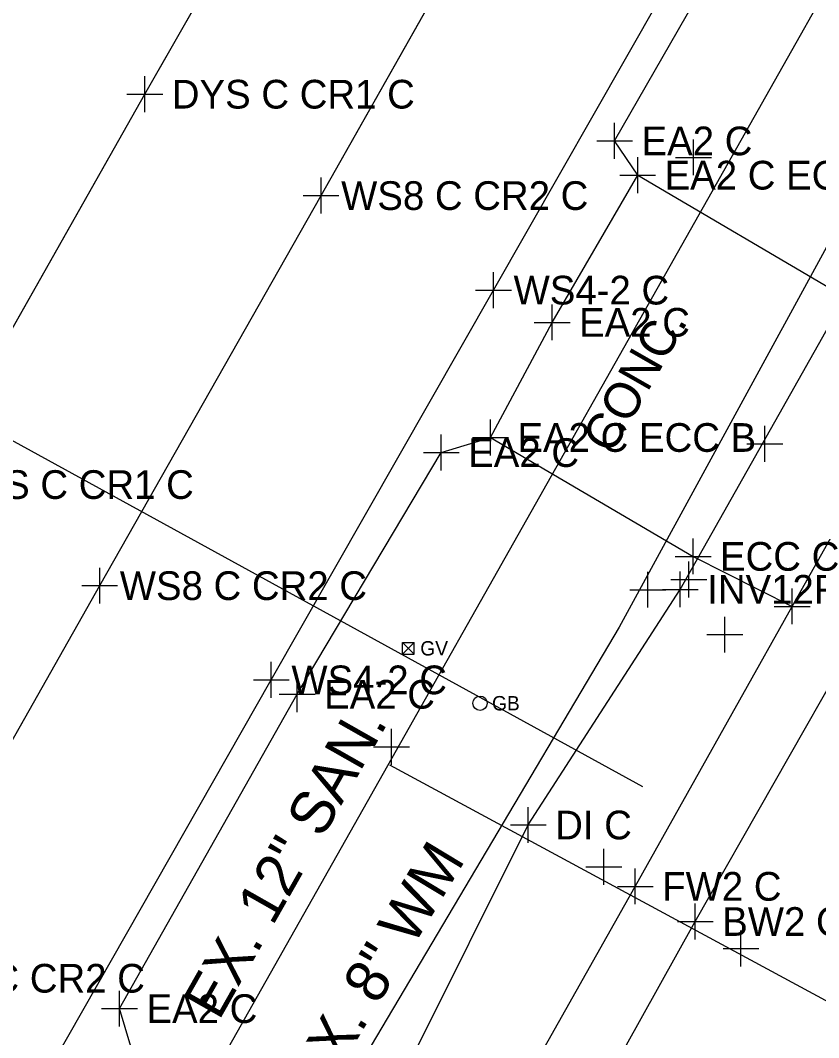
# Model space of a CAD drawing. Extents: x 1363693 to 1365209, y 422201 to 424153.
# Drawn here: x 1364106 to 1364150.5, y 422743.1 to 422799.8 of the extents above; entities that cross this region are included whole.
import ezdxf

# ---------------------------------------------------------------- set-up
doc = ezdxf.new("R2010")
doc.units = 0
for name, color, linetype in [('DR_X_Ditch', 7, 'Continuous'), ('DR_X_Storm_Sewer', 7, 'Continuous'), ('O-ALGN-BASELINE-WERK-CL-RW', 7, 'Continuous'), ('O-ALGN-TEXT-BASELINE-WERK-CL-RW', 7, 'Continuous'), ('OWNERS', 7, 'Continuous'), ('PM_X_Channelizing_Line', 7, 'Continuous'), ('PM_X_CL_Double_Solid', 7, 'Continuous'), ('PM_X_Edge_Line', 7, 'Continuous'), ('RD_X_Text', 7, 'Continuous'), ('SV_X_Original_Ground', 7, 'Continuous'), ('SV_X_Shot_Marker', 7, 'Continuous'), ('UT_X_Gas', 7, 'Continuous'), ('UT_X_Gas_Cells', 7, 'Continuous'), ('UT_X_Gas_Text', 7, 'Continuous'), ('UT_X_Sanitary_Line', 7, 'Continuous'), ('UT_X_Sanitary_Text', 7, 'Continuous'), ('UT_X_Water', 7, 'Continuous'), ('UT_X_Water_Text', 7, 'Continuous')]:
    doc.layers.add(name, color=color, linetype=linetype)

msp = doc.modelspace()

# ---------------------------------------------------------------- linework, layer by layer
at = {"layer": 'DR_X_Ditch'}
for p, q in [((1364134.344, 422754.934), (1364142.823, 422768.071)), ((1364134.344, 422754.934), (1364142.823, 422768.071)), ((1364125.178, 422736.61), (1364134.344, 422754.934)), ((1364125.178, 422736.61), (1364134.344, 422754.934))]:
    msp.add_line(p, q, dxfattribs=at)
at = {"layer": 'DR_X_Storm_Sewer'}
msp.add_line((1364142.823, 422768.071), (1364152.801, 422785.755), dxfattribs=at)
msp.add_line((1364142.823, 422768.071), (1364152.801, 422785.755), dxfattribs=at)
at = {"layer": 'O-ALGN-BASELINE-WERK-CL-RW'}
for points in [[(1364063.861, 422708.444), (1364075.973, 422730.252), (1364088.269, 422752.078), (1364100.636, 422773.911), (1364112.961, 422795.674), (1364125.29, 422817.23)], [(1364073.278, 422703.065), (1364085.603, 422724.652), (1364098.051, 422746.39), (1364110.44, 422768.276), (1364122.785, 422790.021), (1364135.008, 422811.616)]]:
    msp.add_lwpolyline(points, dxfattribs=at)
at = {"layer": 'O-ALGN-TEXT-BASELINE-WERK-CL-RW'}
for points in [[(1364106.881, 422684.697), (1364119.186, 422706.188), (1364124.526, 422715.531), (1364131.747, 422728.163), (1364132.791, 422730.069), (1364143.66, 422749.553), (1364152.461, 422765.008), (1364156.109, 422771.56), (1364160.497, 422779.388), (1364168.274, 422793.373), (1364180.613, 422814.721), (1364181.642, 422816.657), (1364190.312, 422832.027), (1364193.051, 422836.798), (1364205.158, 422858.42), (1364210.927, 422868.703), (1364217.538, 422880.583), (1364219, 422883.263), (1364226.216, 422896.876), (1364226.216, 422896.876), (1364230.124, 422904.765), (1364230.124, 422904.765), (1364238.068, 422921.555)], [(1364103.528, 422686.802), (1364115.786, 422708.146), (1364121.111, 422717.426), (1364128.281, 422730.151), (1364129.454, 422732.257), (1364140.312, 422751.513), (1364149.061, 422767.123), (1364152.636, 422773.448), (1364157.186, 422781.325), (1364164.964, 422795.393), (1364177.23, 422816.837)]]:
    msp.add_lwpolyline(points, dxfattribs=at)
at = {"layer": 'OWNERS'}
for points in [[(1364084.38, 422697.084), (1364096.639, 422718.672), (1364099.659, 422723.794), (1364104.078, 422727.14), (1364111.127, 422739.357), (1364112.498, 422741.524), (1364111.547, 422744.697), (1364121.455, 422762.22), (1364129.492, 422775.694), (1364132.238, 422776.536), (1364135.676, 422782.955), (1364140.445, 422791.159), (1364139.16, 422793.068), (1364146.3, 422805.509)], [(1364140.445, 422791.159), (1364151.778, 422784.5), (1364157.186, 422781.325)], [(1364132.238, 422776.536), (1364143.536, 422769.908), (1364149.061, 422767.123)]]:
    msp.add_lwpolyline(points, dxfattribs=at)
at = {"layer": 'PM_X_Channelizing_Line'}
for p, q in [((1364112.961, 422795.674), (1364125.29, 422817.23)), ((1364122.785, 422790.021), (1364135.008, 422811.616)), ((1364122.785, 422790.021), (1364135.008, 422811.616)), ((1364132.404, 422784.75), (1364144.749, 422806.393)), ((1364100.636, 422773.911), (1364112.961, 422795.674)), ((1364110.44, 422768.276), (1364122.785, 422790.021)), ((1364110.44, 422768.276), (1364122.785, 422790.021)), ((1364120.011, 422763.024), (1364132.404, 422784.75)), ((1364098.051, 422746.39), (1364110.44, 422768.276)), ((1364098.051, 422746.39), (1364110.44, 422768.276)), ((1364107.662, 422741.373), (1364120.011, 422763.024))]:
    msp.add_line(p, q, dxfattribs=at)
at = {"layer": 'PM_X_CL_Double_Solid'}
for p, q in [((1364112.961, 422795.674), (1364125.29, 422817.23)), ((1364100.636, 422773.911), (1364112.961, 422795.674))]:
    msp.add_line(p, q, dxfattribs=at)
at = {"layer": 'PM_X_Edge_Line'}
for p, q in [((1364132.404, 422784.75), (1364144.749, 422806.393)), ((1364120.011, 422763.024), (1364132.404, 422784.75)), ((1364107.662, 422741.373), (1364120.011, 422763.024))]:
    msp.add_line(p, q, dxfattribs=at)
at = {"layer": 'SV_X_Original_Ground'}
for p, q in [((1364112.961, 422794.674), (1364112.961, 422796.674)), ((1364111.961, 422795.674), (1364113.961, 422795.674)), ((1364143.562, 422791.152), (1364143.562, 422793.152)), ((1364142.562, 422792.152), (1364144.562, 422792.152)), ((1364122.785, 422789.021), (1364122.785, 422791.021)), ((1364121.785, 422790.021), (1364123.785, 422790.021)), ((1364132.404, 422783.75), (1364132.404, 422785.75)), ((1364131.404, 422784.75), (1364133.404, 422784.75)), ((1364147.536, 422775.185), (1364147.536, 422777.185)), ((1364146.536, 422776.185), (1364148.536, 422776.185)), ((1364143.302, 422767.62), (1364143.302, 422769.62)), ((1364110.44, 422767.276), (1364110.44, 422769.276)), ((1364141.014, 422767.05), (1364141.014, 422769.05)), ((1364109.44, 422768.276), (1364111.44, 422768.276)), ((1364142.302, 422768.62), (1364144.302, 422768.62)), ((1364140.014, 422768.05), (1364142.014, 422768.05)), ((1364145.304, 422764.547), (1364145.304, 422766.547)), ((1364144.304, 422765.547), (1364146.304, 422765.547)), ((1364120.011, 422762.024), (1364120.011, 422764.024)), ((1364119.011, 422763.024), (1364121.011, 422763.024)), ((1364126.719, 422758.288), (1364126.719, 422760.288)), ((1364125.719, 422759.288), (1364127.719, 422759.288)), ((1364138.557, 422751.597), (1364138.557, 422753.597)), ((1364137.557, 422752.597), (1364139.557, 422752.597)), ((1364146.208, 422747.053), (1364146.208, 422749.053)), ((1364145.208, 422748.053), (1364147.208, 422748.053))]:
    msp.add_line(p, q, dxfattribs=at)
at = {"layer": 'SV_X_Shot_Marker'}
for p, q in [((1364139.16, 422792.068), (1364139.16, 422794.068)), ((1364138.16, 422793.068), (1364140.16, 422793.068)), ((1364140.445, 422790.159), (1364140.445, 422792.159)), ((1364139.445, 422791.159), (1364141.445, 422791.159)), ((1364135.676, 422781.955), (1364135.676, 422783.955)), ((1364134.676, 422782.955), (1364136.676, 422782.955)), ((1364132.238, 422775.536), (1364132.238, 422777.536)), ((1364129.492, 422774.694), (1364129.492, 422776.694)), ((1364131.238, 422776.536), (1364133.238, 422776.536)), ((1364128.492, 422775.694), (1364130.492, 422775.694)), ((1364143.536, 422768.908), (1364143.536, 422770.908)), ((1364142.536, 422769.908), (1364144.536, 422769.908)), ((1364142.823, 422767.071), (1364142.823, 422769.071)), ((1364141.823, 422768.071), (1364143.823, 422768.071)), ((1364149.061, 422766.123), (1364149.061, 422768.123)), ((1364148.061, 422767.123), (1364150.061, 422767.123)), ((1364121.455, 422761.22), (1364121.455, 422763.22)), ((1364120.455, 422762.22), (1364122.455, 422762.22)), ((1364134.344, 422753.934), (1364134.344, 422755.934)), ((1364133.344, 422754.934), (1364135.344, 422754.934)), ((1364140.312, 422750.513), (1364140.312, 422752.513)), ((1364139.312, 422751.513), (1364141.312, 422751.513)), ((1364143.66, 422748.553), (1364143.66, 422750.553)), ((1364142.66, 422749.553), (1364144.66, 422749.553)), ((1364111.547, 422743.697), (1364111.547, 422745.697)), ((1364110.547, 422744.697), (1364112.547, 422744.697))]:
    msp.add_line(p, q, dxfattribs=at)
at = {"layer": 'UT_X_Gas'}
msp.add_line((1364140.727, 422757.062), (1364089.821, 422785.007), dxfattribs=at)
at = {"layer": 'UT_X_Gas_Cells'}
for p, q in [((1364127.32, 422764.45), (1364127.985, 422765.116)), ((1364127.32, 422765.116), (1364127.985, 422764.45)), ((1364127.32, 422765.116), (1364127.985, 422765.116)), ((1364127.32, 422764.45), (1364127.32, 422765.116)), ((1364127.985, 422764.45), (1364127.985, 422765.116)), ((1364127.32, 422764.45), (1364127.985, 422764.45))]:
    msp.add_line(p, q, dxfattribs=at)
msp.add_circle((1364131.653, 422761.723), 0.4, dxfattribs=at)
at = {"layer": 'UT_X_Sanitary_Line'}
msp.add_line((1364126.607, 422758.296), (1364154.16, 422743.397), dxfattribs=at)
msp.add_lwpolyline([(1364014.261, 422733.758), (1364095.069, 422702.67), (1364258.083, 422991.019), (1364292.624, 423022.755)], dxfattribs=at)
at = {"layer": 'UT_X_Water'}
msp.add_lwpolyline([(1364263.889, 423134.469), (1364270.338, 423133.178), (1364266, 423070.885), (1364241.238, 422967.415), (1364211.801, 422898.599), (1364139.416, 422765.962), (1364094.46, 422690.2)], dxfattribs=at)

# ---------------------------------------------------------------- texts
at = {"layer": 'RD_X_Text'}
msp.add_text('CONC.', height=2, rotation=60.281, dxfattribs=at).set_placement((1364138.999, 422775.535))
at = {"layer": 'SV_X_Original_Ground'}
for s, p in [('DYS C CR1 C', (1364114.461, 422794.874)), ('WS8 C CR2 C', (1364123.904, 422789.221)), ('WS4-2 C', (1364133.523, 422783.95)), ('DYS C CR1 C', (1364102.136, 422773.111)), ('WS8 C CR2 C', (1364111.559, 422767.476)), ('WS4-2 C', (1364121.13, 422762.224)), ('WS8 C CR2 C', (1364099.17, 422745.59))]:
    msp.add_text(s, height=1.6, dxfattribs=at).set_placement(p)
at = {"layer": 'SV_X_Shot_Marker'}
for s, p in [('EA2 C', (1364140.66, 422792.268)), ('EA2 C ECC B', (1364141.945, 422790.359)), ('EA2 C', (1364137.176, 422782.155)), ('EA2 C ECC B', (1364133.738, 422775.736)), ('EA2 C', (1364130.992, 422774.894)), ('ECC C', (1364145.036, 422769.108)), ('INV12RCP DI E', (1364144.323, 422767.271)), ('EA2 C', (1364122.955, 422761.42)), ('DI C', (1364135.844, 422754.134)), ('FW2 C', (1364141.812, 422750.713)), ('BW2 C', (1364145.16, 422748.753)), ('EA2 C', (1364113.047, 422743.897))]:
    msp.add_text(s, height=1.6, dxfattribs=at).set_placement(p)
at = {"layer": 'UT_X_Gas_Text'}
for s, p in [('GV', (1364128.321, 422764.383)), ('GB', (1364132.321, 422761.323))]:
    msp.add_text(s, height=0.8, dxfattribs=at).set_placement(p)
at = {"layer": 'UT_X_Sanitary_Text'}
msp.add_text('EX. 12" SAN.', height=2.4, rotation=60.4454, dxfattribs=at).set_placement((1364117.088, 422743.984))
at = {"layer": 'UT_X_Water_Text'}
msp.add_text('EX. 8" WM', height=2.4, rotation=58.8703, dxfattribs=at).set_placement((1364122.806, 422739.656))

doc.saveas('drawing.dxf')
